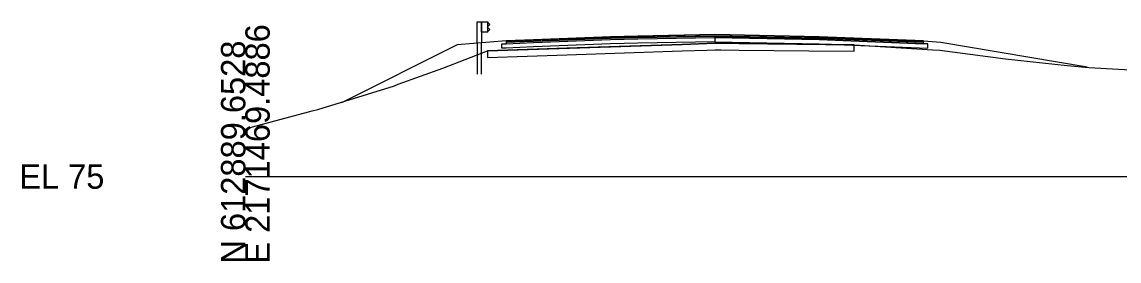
# Model space of a CAD drawing. Extents: x -26 to 1303, y -3010 to 12023.
# Drawn here: x -25.7 to 100.5, y 5990.3 to 6017.7 of the extents above; entities that cross this region are included whole.
import ezdxf

# ---------------------------------------------------------------- set-up
doc = ezdxf.new("R2010")
doc.units = 0
for name, color, linetype in [('RD_GPK_XS_Cell', 7, 'Continuous'), ('RD_PD_Final_TrvlWay', 7, 'Continuous'), ('RD_XS_Base', 7, 'Continuous'), ('RD_XS_ExGround', 7, 'Continuous'), ('RD_XS_ExPaveRet', 7, 'Continuous'), ('RD_XS_GR', 7, 'Continuous'), ('RD_XS_Greenside', 7, 'Continuous'), ('RD_XS_Pave', 7, 'Continuous'), ('RD_XS_PaveOvlay_CP', 7, 'Continuous'), ('RD_XS_TieSlope', 7, 'Continuous')]:
    doc.layers.add(name, color=color, linetype=linetype)

msp = doc.modelspace()

# ---------------------------------------------------------------- linework, layer by layer
at = {"layer": 'RD_GPK_XS_Cell'}
msp.add_line((0, 6000), (150, 6000), dxfattribs=at)
at = {"layer": 'RD_PD_Final_TrvlWay'}
msp.add_lwpolyline([(27.17, 6011.74), (27.17, 6015.35), (26.67, 6015.31), (26.67, 6011.74)], dxfattribs=at)
at = {"layer": 'RD_XS_Base'}
for p, q in [((45.12, 6015.8), (54, 6015.97)), ((54, 6016.01), (54, 6016.13)), ((54, 6016.13), (54, 6015.64)), ((54, 6015.97), (54, 6016.13)), ((54, 6016.13), (54, 6015.47)), ((54, 6015.97), (54, 6016.01)), ((54, 6015.97), (54, 6015.6)), ((54, 6015.97), (54, 6015.47)), ((66, 6015.73), (54, 6015.97)), ((54, 6015.97), (54, 6015.97)), ((29.5, 6015.23), (29.63, 6015.24)), ((29.5, 6014.86), (29.5, 6015.23)), ((29.5, 6014.73), (29.5, 6014.86)), ((29.63, 6014.74), (29.5, 6014.73)), ((29.63, 6015.24), (30, 6015.25)), ((30, 6014.75), (29.63, 6014.74)), ((30, 6015.25), (33.12, 6015.38)), ((33.12, 6014.88), (30, 6014.75)), ((33.12, 6015.38), (42, 6015.73)), ((42, 6015.23), (33.12, 6014.88)), ((42, 6015.73), (45.12, 6015.8)), ((45.12, 6015.3), (42, 6015.23)), ((54, 6015.47), (45.12, 6015.3)), ((54, 6015.64), (54, 6015.47)), ((54, 6015.6), (54, 6015.47)), ((54, 6015.47), (54, 6015.47)), ((54, 6015.47), (54, 6015.47)), ((54, 6015.47), (66, 6015.23)), ((78, 6015.25), (66, 6015.73)), ((66, 6015.23), (78.5, 6014.73)), ((68, 6015.65), (68, 6015.65)), ((68, 6015.15), (68, 6015.15)), ((78.5, 6015.23), (78, 6015.25)), ((78, 6015.25), (78, 6015.25)), ((78.5, 6014.73), (78.5, 6015.23)), ((78.5, 6015.23), (78.5, 6015.23)), ((78.5, 6014.73), (78.5, 6014.73)), ((78.5, 6014.73), (78.5, 6014.73))]:
    msp.add_line(p, q, dxfattribs=at)
at = {"layer": 'RD_XS_ExGround'}
msp.add_lwpolyline([(0, 6005.43), (0.84, 6005.69), (7.25, 6007.44), (7.67, 6007.53), (8.33, 6007.71), (17.14, 6010.43), (17.59, 6010.61), (22.72, 6012.45), (27.85, 6014.42), (50.25, 6015.17), (54.03, 6015.3), (56.79, 6015.27), (70.03, 6015.13), (79.03, 6014.55), (79.85, 6014.51), (81.31, 6014.33), (87.43, 6013.5), (94.52, 6012.73), (97.02, 6012.53), (104.5, 6012.1)], dxfattribs=at)
at = {"layer": 'RD_XS_ExPaveRet'}
msp.add_lwpolyline([(56.79, 6015.27), (54.7, 6015.3), (54.03, 6015.3), (53.12, 6015.27), (50.25, 6015.17), (36.98, 6014.73), (27.85, 6014.42), (27.85, 6014.42), (27.85, 6014.42), (27.85, 6014.01), (27.85, 6013.67), (27.85, 6013.67), (27.85, 6013.67), (36.98, 6013.98), (50.25, 6014.42), (53.12, 6014.52), (54.03, 6014.55), (54.7, 6014.55), (56.79, 6014.52), (64.8, 6014.43), (70.03, 6014.38), (70.03, 6014.72), (70.03, 6015.13), (64.8, 6015.18), (56.79, 6015.27)], dxfattribs=at)
msp.add_lwpolyline([(56.79, 6015.27), (54.7, 6015.3), (54.03, 6015.3), (53.12, 6015.27), (50.25, 6015.17), (36.98, 6014.73), (27.85, 6014.42), (27.85, 6014.42), (27.85, 6014.42), (27.85, 6014.01), (27.85, 6013.67), (27.85, 6013.67), (27.85, 6013.67), (36.98, 6013.98), (50.25, 6014.42), (53.12, 6014.52), (54.03, 6014.55), (54.7, 6014.55), (56.79, 6014.52), (64.8, 6014.43), (70.03, 6014.38), (70.03, 6014.72), (70.03, 6015.13), (64.8, 6015.18), (56.79, 6015.27)], dxfattribs=at)
at = {"layer": 'RD_XS_GR'}
for p, q in [((26.67, 6015.31), (26.67, 6017.74)), ((26.67, 6017.74), (26.92, 6017.74)), ((26.92, 6017.74), (27.17, 6017.74)), ((27.17, 6017.74), (27.17, 6015.35)), ((27.17, 6016.57), (27.17, 6017.74)), ((27.17, 6017.74), (27.83, 6017.74)), ((27.83, 6017.74), (27.83, 6016.57)), ((28.03, 6017.52), (27.83, 6017.74)), ((27.83, 6017.74), (27.83, 6016.88)), ((27.83, 6017.16), (27.9, 6017.23)), ((28.03, 6016.94), (27.83, 6017.16)), ((27.9, 6017.23), (28.1, 6017.45)), ((28.1, 6017.45), (28.03, 6017.52)), ((27.83, 6016.57), (27.17, 6016.57)), ((27.83, 6016.88), (27.83, 6016.57)), ((27.83, 6016.57), (27.9, 6016.65)), ((27.9, 6016.65), (28.1, 6016.86)), ((28.1, 6016.86), (28.03, 6016.94)), ((27.17, 6015.35), (26.67, 6015.31))]:
    msp.add_line(p, q, dxfattribs=at)
at = {"layer": 'RD_XS_Greenside'}
for p, q in [((24.35, 6015.12), (11.04, 6008.46)), ((80, 6015.41), (96.83, 6012.61))]:
    msp.add_line(p, q, dxfattribs=at)
at = {"layer": 'RD_XS_Pave'}
for p, q in [((42, 6016.05), (33.12, 6015.7)), ((42, 6015.89), (33.12, 6015.54)), ((33.12, 6015.54), (42, 6015.89)), ((45.12, 6016.11), (42, 6016.05)), ((45.12, 6015.95), (42, 6015.89)), ((42, 6015.89), (45.12, 6015.95)), ((54, 6016.29), (45.12, 6016.11)), ((54, 6016.13), (45.12, 6015.95)), ((45.12, 6015.95), (54, 6016.13)), ((45.12, 6015.8), (54, 6015.97)), ((66, 6016.05), (54, 6016.29)), ((54, 6016.01), (54, 6016.13)), ((54, 6016.13), (54, 6016.01)), ((54, 6015.97), (54, 6016.13)), ((54, 6016.13), (66, 6015.89)), ((66, 6015.89), (54, 6016.13)), ((54, 6016.13), (54, 6015.97)), ((54, 6015.97), (54, 6016.01)), ((54, 6016.01), (54, 6015.97)), ((54, 6015.97), (54, 6015.97)), ((54, 6015.97), (54, 6015.97)), ((54, 6015.97), (66, 6015.73)), ((78, 6015.57), (66, 6016.05)), ((66, 6015.89), (78, 6015.41)), ((78, 6015.41), (66, 6015.89)), ((68, 6015.97), (68, 6015.97)), ((33.12, 6015.7), (30, 6015.57)), ((30, 6015.57), (30, 6015.45)), ((33.12, 6015.54), (30, 6015.41)), ((30, 6015.41), (33.12, 6015.54)), ((30, 6015.45), (30, 6015.41)), ((30, 6015.41), (30, 6015.3)), ((30, 6015.25), (33.12, 6015.38)), ((30, 6015.3), (30, 6015.25)), ((33.12, 6015.38), (42, 6015.73)), ((42, 6015.73), (45.12, 6015.8)), ((66, 6015.73), (78, 6015.25)), ((68, 6015.81), (68, 6015.81)), ((68, 6015.81), (68, 6015.81)), ((68, 6015.65), (68, 6015.65)), ((78, 6015.41), (78, 6015.57)), ((78, 6015.57), (78, 6015.57)), ((78, 6015.41), (78, 6015.41)), ((78, 6015.41), (78, 6015.41)), ((78, 6015.25), (78, 6015.41)), ((78, 6015.41), (78, 6015.41)), ((78, 6015.25), (78, 6015.25)), ((78, 6015.25), (78, 6015.25))]:
    msp.add_line(p, q, dxfattribs=at)
at = {"layer": 'RD_XS_PaveOvlay_CP'}
for p, q in [((30, 6015.57), (42, 6016.05)), ((42, 6016.05), (54, 6016.29)), ((54, 6016.29), (66, 6016.05)), ((66, 6016.05), (78, 6015.57))]:
    msp.add_line(p, q, dxfattribs=at)
at = {"layer": 'RD_XS_TieSlope'}
for p, q in [((30, 6015.57), (24.35, 6015.12)), ((78, 6015.57), (80, 6015.41))]:
    msp.add_line(p, q, dxfattribs=at)

# ---------------------------------------------------------------- texts
at = {"layer": 'RD_GPK_XS_Cell'}
for s, p in [('E 2171469.4886', (2.8, 5990)), ('N 612889.6528', (0, 5990))]:
    msp.add_text(s, height=2.8, rotation=90, dxfattribs=at).set_placement(p)
msp.add_text('EL 75', height=2.8, dxfattribs=at).set_placement((-26, 5998.6))

doc.saveas('drawing.dxf')
